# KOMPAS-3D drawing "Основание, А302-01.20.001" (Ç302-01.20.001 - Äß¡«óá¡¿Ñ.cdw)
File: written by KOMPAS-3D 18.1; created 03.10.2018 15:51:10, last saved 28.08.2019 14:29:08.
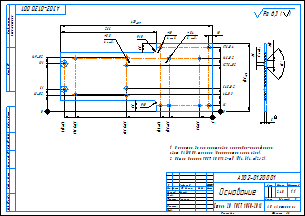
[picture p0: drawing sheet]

Sheet 1: A3, landscape

Document properties: Полное имя файла: D:\Мембранные насосы\Мембранный электропривод\А302-00.00.000 - ASTRA-302 (МЭ200)\3Д ПВХ\А302-01.20.001 - Основание.cdw; Масса: 2.48169

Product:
- Part/product: Основание  | designation А302-01.20.001
    Материал: Сталь 20  ГОСТ 1050-2013 (density 7820 kg/m3)
    Масса: 2.48169
    Раздел спецификации: Детали
    Форматы листов документа: A3
    source file: А302-01.20.001 - Основание.cdw

Title block, sheet 1: Наименование: Основание; designation: А302-01.20.001; Материал: Сталь 20  ГОСТ 1050-2013; Масса: 2,48; scale: 1:1; Количество листов документа: 1; organisation: АО «Астерион»; Форматы листов документа: A3; stored path: \\192.168.87.28\Konstructor_doc\Мембранные насосы\Мембранный электропривод\А302-00.00.000 - ASTRA-302 (МЭ200)\3Д ПВХ\А302-00.20.001 - Основание.cdw; Разработал: Милов; Т. контр.: Лучихин

Views: Вид 1, Сзади, Проекционный вид 2, Местный разрез 1
Referenced files in \\192.168.87.28\Konstructor_doc\Мембранные насосы\Мембранный электропривод\А302-00.00.000 - ASTRA-302 (МЭ200)\3Д ПВХ\: А302-01.20.001 - Основание.m3d
Referenced files in D:\Мембранные насосы\Мембранный электропривод\А302-00.00.000 - ASTRA-302 (МЭ200)\3Д ПВХ\: А302-01.20.001 - Основание.m3d
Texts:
  Ra 6,3
  Ra 6,3 ( )
  Лифлянд
Dimensions and other numbers on the sheet: 35±0,2; 120±0,2; 238,5±0,2; 379,5±0,3; 410±0,4; 10; 144±0,4; 16; 46±0,3; 146±0,2; 176±0,4; 43±0,2; 149±0,2; 61; 131; 64,5±0,2; 127,5±0,2; 4 отв.; 8,4; 6 отв.; 8,8; 188; 29; 25; 266; 420; 8; 5; 18; 2 отв.; 1; 1:1; 2,48; 28.08.2019

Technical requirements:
  Покрытие: Эмаль порошковая эпоксидно-полиэфирная,
  цвет RAL5005, шагрень (допускается глянцевая).
  Общие допуски ГОСТ 30893.2-mK (H14, h14,  t2/2).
